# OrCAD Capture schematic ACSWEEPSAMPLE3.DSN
size A
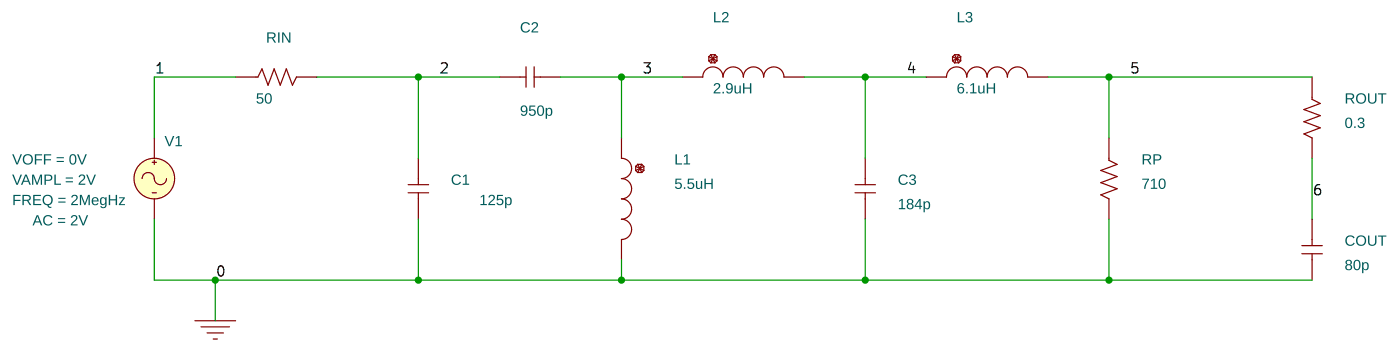
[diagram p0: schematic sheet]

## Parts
C1  125p  [RAD/CK05]
C2  950p  [RAD/CK05]
C3  184p  [RAD/CK05]
COUT  80p  [RAD/CK05]
L1  5.5uH  [DISC/.350x.175/LS.200x.100/.034]
L2  2.9uH  [DISC/.350x.175/LS.200x.100/.034]
L3  6.1uH  [DISC/.350x.175/LS.200x.100/.034]
RIN  50  [AX/RC05]
ROUT  0.3  [AX/RC05]
RP  710  [AX/RC05]
V1  VSIN

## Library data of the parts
C1-C3 COUT = C
L1-L3 = L
RIN ROUT RP = R
V1 = VSIN: AC: 2V; FREQ: 2MegHz; VAMPL: 2V; VOFF: 0V

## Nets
0: C1.2 C3.2 COUT.2 L1.2 RP.2 V1.2(-)
1: RIN.1 V1.1(+)
2: C1.1 C2.1 RIN.2
3: C2.2 L1.1 L2.1
4: C3.1 L2.2 L3.1
5: L3.2 ROUT.1 RP.1
6: COUT.1 ROUT.2
